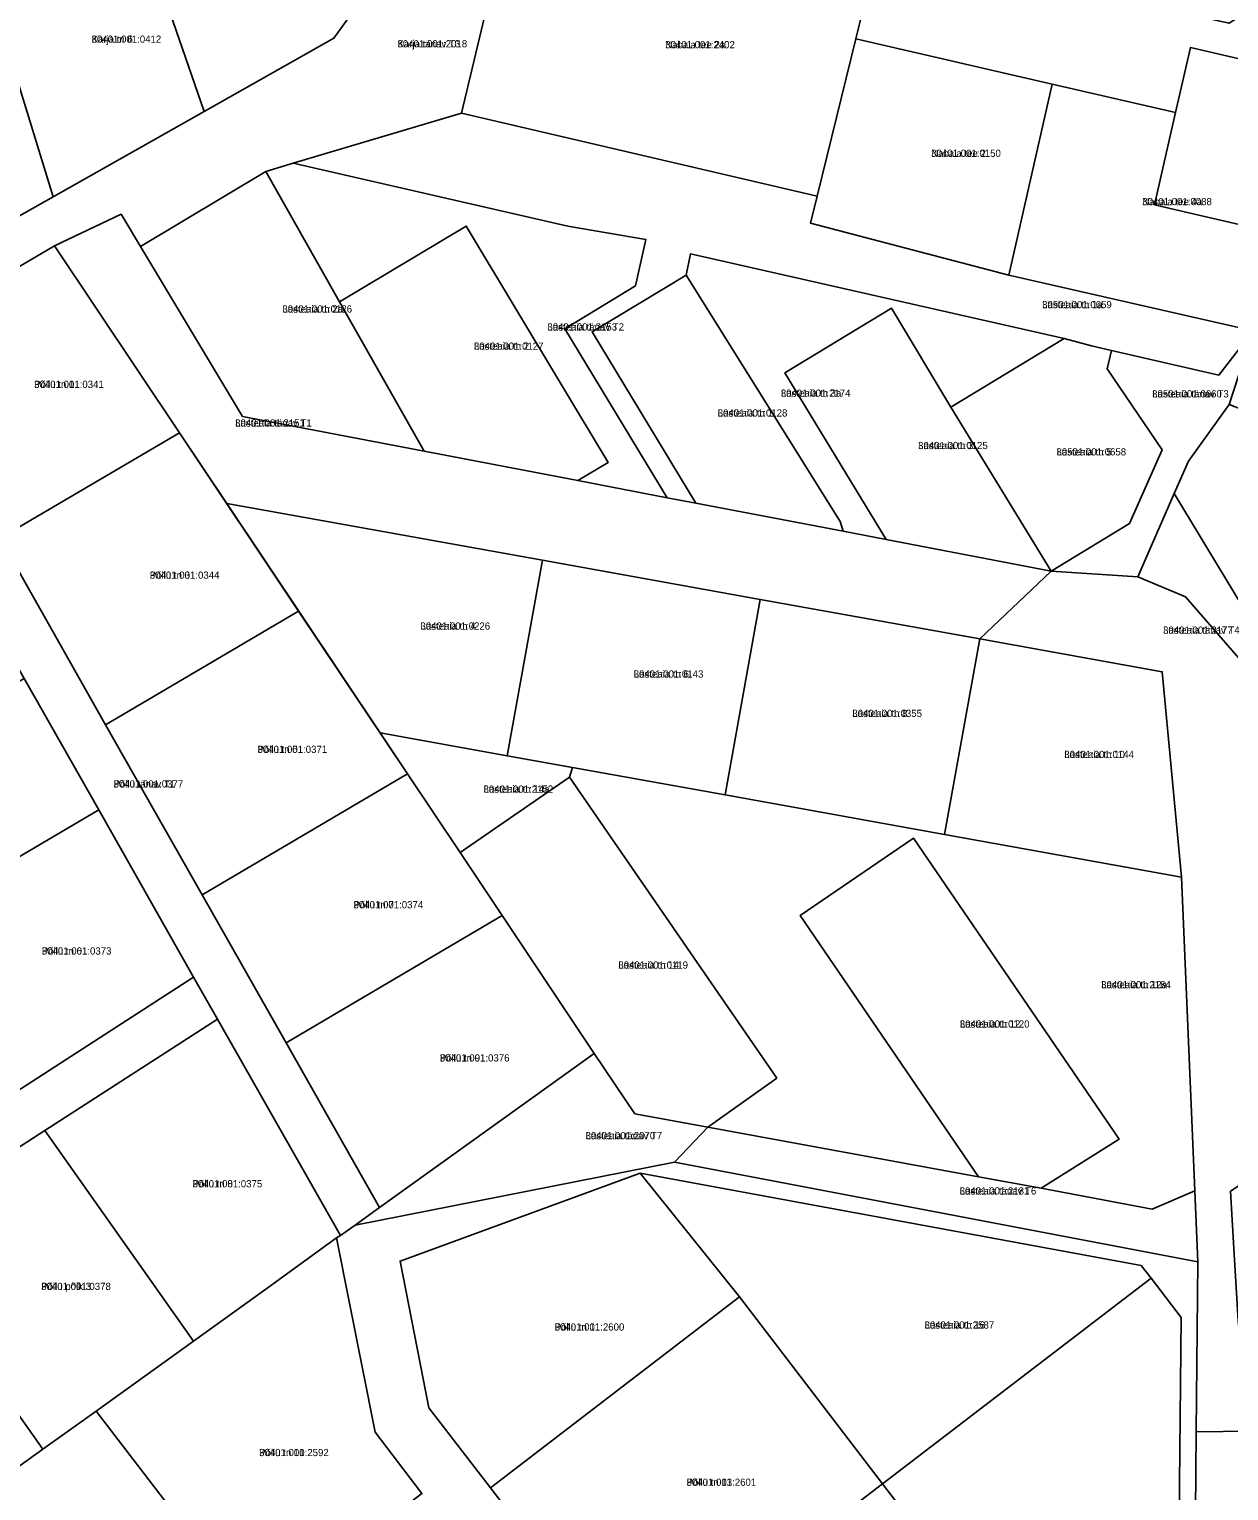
# Model space of a CAD drawing. Extents: x 542681 to 554572, y 6566489 to 6580482.
# Drawn here: x 547431.8 to 547681.6, y 6574390.7 to 6574695.1 of the extents above; entities that cross this region are included whole.
import ezdxf

# ---------------------------------------------------------------- set-up
doc = ezdxf.new("R2010")
doc.units = 0
for name, color, linetype in [('L_AADRESS', 7, 'Continuous'), ('PIIR', 7, 'Continuous'), ('TUNNUS', 7, 'Continuous')]:
    doc.layers.add(name, color=color, linetype=linetype)

msp = doc.modelspace()

# ---------------------------------------------------------------- linework, layer by layer
at = {"layer": 'PIIR'}
for points in [[(547452.73, 6574723.01), (547483.83, 6574735.47), (547497.95, 6574696.99), (547495.27, 6574693.18), (547468.28, 6574677.94)], [(547570.79, 6574730.49), (547571.21, 6574724.16), (547573.28, 6574719.74), (547681.62, 6574696.3), (547693.24, 6574703.84), (547701.71, 6574696.78), (547699.02, 6574685.37), (547673.6, 6574691.27), (547670.48, 6574677.72), (547644.79, 6574683.65), (547603.92, 6574693.1), (547606.83, 6574705.08), (547564.79, 6574715.05)], [(547421.34, 6574710.43), (547452.73, 6574723.01), (547468.28, 6574677.94), (547436.78, 6574660.15)], [(547595.88, 6574660.3), (547521.8, 6574677.56), (547532.2, 6574721.24), (547535.48, 6574721.91), (547564.79, 6574715.05), (547606.83, 6574705.08), (547603.92, 6574693.1)], [(547390.11, 6574701.19), (547420.44, 6574713.35), (547421.34, 6574710.43), (547436.78, 6574660.15), (547407.75, 6574643.76), (547399.09, 6574671.97)], [(547603.92, 6574693.1), (547644.79, 6574683.65), (547635.74, 6574643.87), (547594.5, 6574654.66), (547595.88, 6574660.3)], [(547666.08, 6574658.52), (547670.48, 6574677.72), (547673.6, 6574691.27), (547699.02, 6574685.37), (547698.4, 6574682.68), (547703.97, 6574681.38), (547696.95, 6574651.68), (547691.43, 6574652.97), (547691.33, 6574652.54), (547688.21, 6574653.33), (547675.3, 6574656.35)], [(547670.48, 6574677.72), (547666.08, 6574658.52), (547675.3, 6574656.35), (547688.21, 6574653.33), (547691.33, 6574652.54), (547686.63, 6574632.27), (547635.74, 6574643.87), (547644.79, 6574683.65)], [(547686.63, 6574632.27), (547679.49, 6574623.06), (547657.17, 6574628.16), (547652.97, 6574629.12), (547647.28, 6574630.67), (547569.49, 6574648.27), (547568.57, 6574643.82), (547549, 6574632.04), (547570.61, 6574596.39), (547564.66, 6574597.51), (547543.35, 6574632.67), (547558.04, 6574641.6), (547560.19, 6574651.29), (547543.94, 6574654.09), (547486.8, 6574667.15), (547521.8, 6574677.56), (547595.88, 6574660.3), (547594.5, 6574654.66), (547635.74, 6574643.87)], [(547481.06, 6574665.45), (547496.45, 6574638.29), (547514.08, 6574607.18), (547476.26, 6574614.41), (547455.01, 6574649.8)], [(547564.66, 6574597.51), (547546.07, 6574601.07), (547552.34, 6574604.83), (547522.81, 6574654.09), (547496.45, 6574638.29), (547481.06, 6574665.45), (547486.8, 6574667.15), (547543.94, 6574654.09), (547560.19, 6574651.29), (547558.04, 6574641.6), (547543.35, 6574632.67)], [(547437.08, 6574649.97), (547450.96, 6574656.55), (547455.01, 6574649.8), (547476.26, 6574614.41), (547514.08, 6574607.18), (547546.07, 6574601.07), (547564.66, 6574597.51), (547570.61, 6574596.39), (547601.31, 6574590.51), (547610.23, 6574588.81), (547644.58, 6574582.24), (547629.7, 6574568.1), (547584.01, 6574576.33), (547538.66, 6574584.49), (547472.94, 6574596.32), (547463.09, 6574611.05)], [(547522.81, 6574654.09), (547552.34, 6574604.83), (547546.07, 6574601.07), (547514.08, 6574607.18), (547496.45, 6574638.29)], [(547402.6, 6574629.69), (547437.08, 6574649.97), (547463.09, 6574611.05), (547425.68, 6574589.05)], [(547610.23, 6574588.81), (547601.31, 6574590.51), (547600.68, 6574592.56), (547568.57, 6574643.82), (547569.49, 6574648.27), (547647.28, 6574630.67), (547623.71, 6574616.36), (547611.32, 6574636.97), (547589.17, 6574623.53)], [(547600.68, 6574592.56), (547601.31, 6574590.51), (547570.61, 6574596.39), (547549, 6574632.04), (547568.57, 6574643.82)], [(547623.71, 6574616.36), (547644.58, 6574582.24), (547610.23, 6574588.81), (547589.17, 6574623.53), (547611.32, 6574636.97)], [(547662.66, 6574581.02), (547644.58, 6574582.24), (547660.86, 6574592.15), (547667.67, 6574607.5), (547656.22, 6574624.37), (547657.17, 6574628.16), (547679.49, 6574623.06), (547686.63, 6574632.27), (547681.65, 6574616.89), (547673.14, 6574605.15), (547670.2, 6574598.38)], [(547393.98, 6574624.62), (547402.6, 6574629.69), (547425.68, 6574589.05), (547447.71, 6574550.23), (547467.81, 6574514.84), (547485.31, 6574484.02), (547504.78, 6574449.71), (547499.66, 6574446.03), (547496.61, 6574443.85), (547471.01, 6574488.95), (547466.06, 6574497.66), (547446.29, 6574532.48), (547430.74, 6574559.87), (547401.05, 6574612.17)], [(547644.58, 6574582.24), (547623.71, 6574616.36), (547647.28, 6574630.67), (547652.97, 6574629.12), (547657.17, 6574628.16), (547656.22, 6574624.37), (547667.67, 6574607.5), (547660.86, 6574592.15)], [(547687.32, 6574614.71), (547689.36, 6574605.14), (547703.04, 6574582.49), (547686, 6574572.2), (547670.2, 6574598.38), (547673.14, 6574605.15), (547681.65, 6574616.89)], [(547425.68, 6574589.05), (547463.09, 6574611.05), (547487.92, 6574573.88), (547447.71, 6574550.23)], [(547670.2, 6574598.38), (547686, 6574572.2), (547708.06, 6574535.64), (547726.61, 6574504.91), (547690.14, 6574482.87), (547689.34, 6574509.9), (547685.03, 6574562.47), (547672.56, 6574576.9), (547662.66, 6574581.02)], [(547472.94, 6574596.32), (547538.66, 6574584.49), (547531.33, 6574543.77), (547504.87, 6574548.53)], [(547584.01, 6574576.33), (547576.68, 6574535.61), (547531.33, 6574543.77), (547538.66, 6574584.49)], [(547644.58, 6574582.24), (547662.66, 6574581.02), (547672.56, 6574576.9), (547685.03, 6574562.47), (547689.34, 6574509.9), (547690.14, 6574482.87), (547706.06, 6574455.86), (547693.15, 6574448.27), (547687.53, 6574456.77), (547681.92, 6574453.09), (547682.63, 6574441.14), (547683.52, 6574426.09), (547686.02, 6574403.1), (547674.8, 6574402.98), (547675.11, 6574438.37), (547674.49, 6574453.16), (547671.7, 6574518.5), (547667.72, 6574561.26), (547629.7, 6574568.1)], [(547447.71, 6574550.23), (547487.92, 6574573.88), (547510.57, 6574539.99), (547467.81, 6574514.84)], [(547584.01, 6574576.33), (547629.7, 6574568.1), (547622.38, 6574527.38), (547576.68, 6574535.61)], [(547667.72, 6574561.26), (547671.7, 6574518.5), (547622.38, 6574527.38), (547629.7, 6574568.1)], [(547386.45, 6574533.81), (547430.74, 6574559.87), (547446.29, 6574532.48), (547402.45, 6574506.69), (547378.88, 6574492.83), (547381.89, 6574509.56)], [(547544.92, 6574541.33), (547544.31, 6574539.29), (547521.51, 6574523.62), (547510.57, 6574539.99), (547504.87, 6574548.53), (547531.33, 6574543.77)], [(547544.94, 6574541.34), (547576.68, 6574535.61), (547622.38, 6574527.38), (547671.7, 6574518.5), (547674.49, 6574453.16), (547665.63, 6574449.35), (547642.52, 6574453.72), (547658.77, 6574463.93), (547615.9, 6574526.61), (547592.36, 6574510.51), (547629.48, 6574456.11), (547573.14, 6574466.43), (547587.45, 6574476.66), (547544.31, 6574539.29)], [(547467.81, 6574514.84), (547510.57, 6574539.99), (547521.51, 6574523.62), (547530.3, 6574510.48), (547485.31, 6574484.02)], [(547587.45, 6574476.66), (547573.14, 6574466.43), (547557.94, 6574469.22), (547549.46, 6574481.8), (547530.3, 6574510.48), (547521.51, 6574523.62), (547544.31, 6574539.29)], [(547402.45, 6574506.69), (547446.29, 6574532.48), (547466.06, 6574497.66), (547426.73, 6574472.26)], [(547658.77, 6574463.93), (547642.52, 6574453.72), (547629.48, 6574456.11), (547592.36, 6574510.51), (547615.9, 6574526.61)], [(547485.31, 6574484.02), (547530.3, 6574510.48), (547549.46, 6574481.8), (547504.78, 6574449.71)], [(547368.1, 6574434.41), (547426.73, 6574472.26), (547466.06, 6574497.66), (547471.01, 6574488.95), (547435.07, 6574465.74), (547402.6, 6574444.78), (547384.35, 6574433), (547382.37, 6574422.8), (547394.83, 6574405.12), (547386.66, 6574399.36), (547383.78, 6574403.45), (547366.8, 6574427.53)], [(547435.07, 6574465.74), (547471.01, 6574488.95), (547496.61, 6574443.85), (547495.83, 6574443.37), (547481.07, 6574432.68), (547466.04, 6574421.88)], [(547504.78, 6574449.71), (547549.46, 6574481.8), (547557.94, 6574469.22), (547573.14, 6574466.43), (547566.2, 6574459.15), (547499.66, 6574446.03)], [(547402.6, 6574444.78), (547435.07, 6574465.74), (547466.04, 6574421.88), (547445.79, 6574407.3), (547434.64, 6574399.34)], [(547573.14, 6574466.43), (547629.48, 6574456.11), (547642.52, 6574453.72), (547665.63, 6574449.35), (547674.49, 6574453.16), (547675.11, 6574438.37), (547566.2, 6574459.15)], [(547509.03, 6574438.52), (547515.01, 6574408.01), (547527.84, 6574391.3), (547557.64, 6574352.41), (547583.06, 6574319.1), (547593.72, 6574317.75), (547639.44, 6574352.96), (547664.17, 6574371.95), (547671.23, 6574385.29), (547671.67, 6574426.76), (547665.39, 6574434.96), (547663.32, 6574437.65), (547559.01, 6574456.83)], [(547515.01, 6574408.01), (547509.03, 6574438.52), (547559.01, 6574456.83), (547579.71, 6574431.06), (547527.84, 6574391.3)], [(547579.71, 6574431.06), (547559.01, 6574456.83), (547663.32, 6574437.65), (547665.39, 6574434.96), (547609.45, 6574392.12)], [(547384.35, 6574433), (547402.6, 6574444.78), (547434.64, 6574399.34), (547402.79, 6574376.48), (547386.66, 6574399.36), (547394.83, 6574405.12), (547382.37, 6574422.8)], [(547479.17, 6574363.77), (547445.79, 6574407.3), (547466.04, 6574421.88), (547481.07, 6574432.68), (547495.83, 6574443.37), (547503.83, 6574402.92), (547513.57, 6574390.11)], [(547639.44, 6574352.96), (547609.45, 6574392.12), (547665.39, 6574434.96), (547671.67, 6574426.76), (547671.23, 6574385.29), (547664.17, 6574371.95)], [(547557.64, 6574352.41), (547527.84, 6574391.3), (547579.71, 6574431.06), (547609.45, 6574392.12)], [(547674.8, 6574402.98), (547686.02, 6574403.1), (547684.85, 6574263.33), (547686.82, 6574244.56), (547734.02, 6574212.5), (547822.03, 6574250.5), (547827.72, 6574239.33), (547809.69, 6574230.27), (547777.69, 6574214.19), (547733.83, 6574194.4), (547727.86, 6574183.54), (547715.37, 6574192.04), (547668.73, 6574223.8), (547673.47, 6574242.5), (547673.47, 6574243.11)], [(547583.06, 6574319.1), (547557.64, 6574352.41), (547609.45, 6574392.12), (547639.44, 6574352.96), (547593.72, 6574317.75)]]:
    msp.add_lwpolyline(points, close=True, dxfattribs=at)
for points in [[(547532.2, 6574721.24), (547521.8, 6574677.56), (547486.8, 6574667.15), (547481.06, 6574665.45), (547455.01, 6574649.8), (547450.96, 6574656.55), (547437.08, 6574649.97), (547402.6, 6574629.69)], [(547407.75, 6574643.76), (547436.78, 6574660.15), (547468.28, 6574677.94), (547495.27, 6574693.18), (547497.95, 6574696.99)], [(547513.57, 6574390.11), (547503.83, 6574402.92), (547495.83, 6574443.37), (547496.61, 6574443.85), (547499.66, 6574446.03), (547566.2, 6574459.15), (547675.11, 6574438.37), (547674.8, 6574402.98), (547673.47, 6574243.11)], [(547402.79, 6574376.48), (547434.64, 6574399.34), (547445.79, 6574407.3), (547479.17, 6574363.77), (547512.01, 6574320.87), (547520.19, 6574310.35), (547471.04, 6574296.29), (547489.28, 6574256.93), (547440.14, 6574241.37), (547421.18, 6574219.95)]]:
    msp.add_lwpolyline(points, dxfattribs=at)

# ---------------------------------------------------------------- texts
at = {"layer": 'L_AADRESS'}
for s, p in [('Karja tn 6', (547444.81, 6574692.26)), ('Karja tänav T3', (547508.5, 6574691.29)), ('Nabala tee 2a', (547564.23, 6574691.11)), ('Nabala tee 2', (547619.61, 6574668.49)), ('Nabala tee 4a', (547663.54, 6574658.43)), ('Lasteaia tn 2a', (547484.54, 6574636.06)), ('Lasteaia tn 1a', (547642.7, 6574636.98)), ('Lasteaia tänav T2', (547539.71, 6574632.33)), ('Lasteaia tn 2', (547524.4, 6574628.33)), ('Põllu tn 1', (547432.85, 6574620.37)), ('Lasteaia tn 3a', (547588.3, 6574618.54)), ('Lasteaia tänav T3', (547665.61, 6574618.39)), ('Lasteaia tänav T1', (547474.7, 6574612.33)), ('Lasteaia tn 1', (547575.16, 6574614.41)), ('Lasteaia tn 3', (547616.88, 6574607.63)), ('Lasteaia tn 5', (547645.69, 6574606.31)), ('Põllu tn 3', (547456.93, 6574580.64)), ('Lasteaia tn 4', (547513.28, 6574570.04)), ('Lasteaia tänav T4', (547667.88, 6574569.19)), ('Lasteaia tn 6', (547557.67, 6574560.05)), ('Lasteaia tn 8', (547603.19, 6574551.85)), ('Põllu tn 5', (547479.35, 6574544.36)), ('Lasteaia tn 10', (547647.32, 6574543.3)), ('Põllu tänav T1', (547449.38, 6574537.16)), ('Lasteaia tn 14a', (547526.41, 6574536.08)), ('Põllu tn 7', (547499.35, 6574512)), ('Põllu tn 6', (547434.44, 6574502.37)), ('Lasteaia tn 14', (547554.48, 6574499.44)), ('Lasteaia tn 12a', (547654.99, 6574495.35)), ('Lasteaia tn 12', (547625.57, 6574487.16)), ('Põllu tn 9', (547517.31, 6574480.1)), ('Lasteaia tänav T7', (547547.65, 6574463.92)), ('Põllu tn 8', (547465.84, 6574453.89)), ('Lasteaia tänav T6', (547625.54, 6574452.4)), ('Põllu põik 3', (547434.32, 6574432.52)), ('Põllu tn 11', (547541.22, 6574424.07)), ('Lasteaia tn 16', (547618.22, 6574424.48)), ('Põllu tn 10', (547479.68, 6574397.92)), ('Põllu tn 13', (547568.68, 6574391.74))]:
    msp.add_text(s, height=1.5, dxfattribs=at).set_placement(p)
at = {"layer": 'TUNNUS'}
for s, p in [('30401:001:0412', (547444.81, 6574692.26)), ('30401:001:2018', (547508.5, 6574691.29)), ('30401:001:2402', (547564.23, 6574691.11)), ('30401:001:0150', (547619.61, 6574668.49)), ('30401:001:0088', (547663.54, 6574658.43)), ('30501:001:0659', (547642.7, 6574636.98)), ('30401:001:0126', (547484.54, 6574636.06)), ('30401:001:2153', (547539.71, 6574632.33)), ('30401:001:0127', (547524.4, 6574628.33)), ('30401:001:0341', (547432.85, 6574620.37)), ('30401:001:2174', (547588.3, 6574618.54)), ('30501:001:0660', (547665.61, 6574618.39)), ('30401:001:2151', (547474.7, 6574612.33)), ('30401:001:0128', (547575.16, 6574614.41)), ('30401:001:0125', (547616.88, 6574607.63)), ('30501:001:0658', (547645.69, 6574606.31)), ('30401:001:0344', (547456.93, 6574580.64)), ('30401:001:0226', (547513.28, 6574570.04)), ('30401:001:2177', (547667.88, 6574569.19)), ('30401:001:0143', (547557.67, 6574560.05)), ('30401:001:0355', (547603.19, 6574551.85)), ('30401:001:0371', (547479.35, 6574544.36)), ('30401:001:0144', (547647.32, 6574543.3)), ('30401:001:0377', (547449.38, 6574537.16)), ('30401:001:2152', (547526.41, 6574536.08)), ('30401:001:0374', (547499.35, 6574512)), ('30401:001:0373', (547434.44, 6574502.37)), ('30401:001:0119', (547554.48, 6574499.44)), ('30401:001:2184', (547654.99, 6574495.35)), ('30401:001:0120', (547625.57, 6574487.16)), ('30401:001:0376', (547517.31, 6574480.1)), ('30401:001:2070', (547547.65, 6574463.92)), ('30401:001:0375', (547465.84, 6574453.89)), ('30401:001:2181', (547625.54, 6574452.4)), ('30401:001:0378', (547434.32, 6574432.52)), ('30401:001:2600', (547541.22, 6574424.07)), ('30401:001:2587', (547618.22, 6574424.48)), ('30401:001:2592', (547479.68, 6574397.92)), ('30401:001:2601', (547568.68, 6574391.74))]:
    msp.add_text(s, height=1.5, dxfattribs=at).set_placement(p)

doc.saveas('drawing.dxf')
